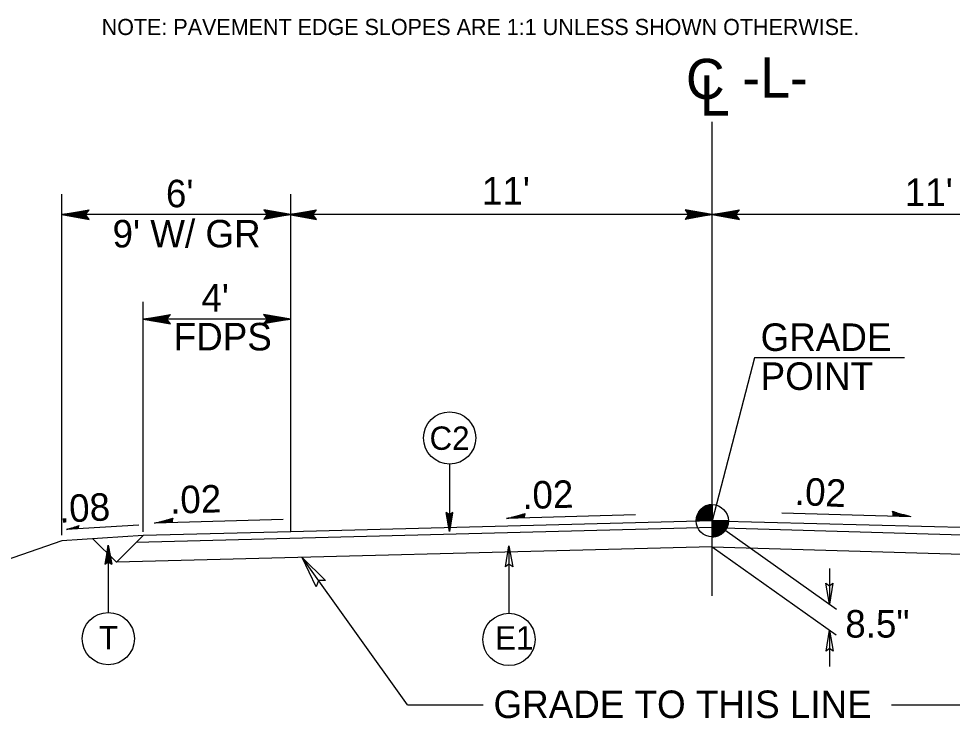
# Model space of a CAD drawing. Extents: x 55823 to 57507, y 47399 to 48499.
# Drawn here: x 56414.9 to 56667.6, y 47890.8 to 48082.1 of the extents above; entities that cross this region are included whole.
import ezdxf

# ---------------------------------------------------------------- set-up
doc = ezdxf.new("R2010")
doc.units = 0
for name, color, linetype in [('Old_Level_1', 7, 'Continuous'), ('Old_Level_11', 7, 'Continuous'), ('Old_Level_2', 7, 'Continuous'), ('Old_Level_20', 7, 'Continuous'), ('Old_Level_3', 7, 'Continuous'), ('Prop Pavement Schedule Description CELL', 7, 'Continuous')]:
    doc.layers.add(name, color=color, linetype=linetype)

msp = doc.modelspace()

# ---------------------------------------------------------------- linework, layer by layer
at = {"layer": 'Old_Level_1'}
for p, q in [((56602.67, 47925.82), (56602.67, 48054.13)), ((56426.62, 47942.28), (56426.62, 48034.56)), ((56488.62, 47943.2), (56488.62, 48034.56)), ((56426.62, 48029.04), (56433.99, 48030.34)), ((56426.62, 48029.04), (56433.85, 48030.15)), ((56433.03, 48029.04), (56433.99, 48030.34)), ((56488.63, 48029.04), (56481.26, 48030.34)), ((56481.26, 48030.34), (56482.22, 48029.04)), ((56481.4, 48030.15), (56488.63, 48029.04)), ((56488.19, 48029.05), (56495.56, 48030.35)), ((56488.19, 48029.05), (56495.42, 48030.16)), ((56494.6, 48029.05), (56495.56, 48030.35)), ((56602.67, 48029.04), (56595.3, 48030.34)), ((56595.3, 48030.34), (56596.26, 48029.04)), ((56595.44, 48030.15), (56602.67, 48029.04)), ((56602.67, 48029.04), (56610.04, 48030.34)), ((56602.67, 48029.04), (56609.9, 48030.15)), ((56609.08, 48029.04), (56610.04, 48030.34)), ((56433.72, 48029.97), (56426.62, 48029.04)), ((56426.62, 48029.04), (56433.58, 48029.78)), ((56433.44, 48029.59), (56426.62, 48029.04)), ((56426.62, 48029.04), (56433.31, 48029.41)), ((56433.17, 48029.23), (56426.62, 48029.04)), ((56426.62, 48029.04), (56433.99, 48027.74)), ((56433.85, 48027.93), (56426.62, 48029.04)), ((56426.62, 48029.04), (56433.72, 48028.11)), ((56433.58, 48028.3), (56426.62, 48029.04)), ((56426.62, 48029.04), (56433.44, 48028.48)), ((56433.31, 48028.67), (56426.62, 48029.04)), ((56426.62, 48029.04), (56433.17, 48028.85)), ((56433.03, 48029.04), (56426.62, 48029.04)), ((56602.67, 48029.04), (56426.62, 48029.04)), ((56433.99, 48027.74), (56433.03, 48029.04)), ((56488.63, 48029.04), (56481.26, 48027.74)), ((56482.22, 48029.04), (56481.26, 48027.74)), ((56488.63, 48029.04), (56481.4, 48027.93)), ((56488.63, 48029.04), (56481.54, 48029.97)), ((56481.54, 48028.11), (56488.63, 48029.04)), ((56481.68, 48029.78), (56488.63, 48029.04)), ((56488.63, 48029.04), (56481.68, 48028.3)), ((56488.63, 48029.04), (56481.81, 48029.6)), ((56481.81, 48028.48), (56488.63, 48029.04)), ((56481.95, 48029.41), (56488.63, 48029.04)), ((56488.63, 48029.04), (56481.95, 48028.67)), ((56488.63, 48029.04), (56482.08, 48029.23)), ((56482.08, 48028.85), (56488.63, 48029.04)), ((56482.22, 48029.04), (56488.63, 48029.04)), ((56495.29, 48029.97), (56488.19, 48029.05)), ((56488.19, 48029.05), (56495.15, 48029.79)), ((56495.01, 48029.6), (56488.19, 48029.05)), ((56488.19, 48029.05), (56494.88, 48029.42)), ((56494.74, 48029.23), (56488.19, 48029.05)), ((56488.19, 48029.05), (56495.56, 48027.75)), ((56495.42, 48027.93), (56488.19, 48029.05)), ((56488.19, 48029.05), (56495.29, 48028.12)), ((56495.15, 48028.3), (56488.19, 48029.05)), ((56488.19, 48029.05), (56495.01, 48028.49)), ((56494.88, 48028.67), (56488.19, 48029.05)), ((56488.19, 48029.05), (56494.74, 48028.86)), ((56494.6, 48029.05), (56488.19, 48029.05)), ((56495.56, 48027.75), (56494.6, 48029.05)), ((56602.67, 48029.04), (56595.3, 48027.74)), ((56596.26, 48029.04), (56595.3, 48027.74)), ((56602.67, 48029.04), (56595.44, 48027.92)), ((56602.67, 48029.04), (56595.58, 48029.97)), ((56595.58, 48028.11), (56602.67, 48029.04)), ((56595.71, 48029.78), (56602.67, 48029.04)), ((56602.67, 48029.04), (56595.71, 48028.3)), ((56602.67, 48029.04), (56595.85, 48029.59)), ((56595.85, 48028.48), (56602.67, 48029.04)), ((56595.98, 48029.41), (56602.67, 48029.04)), ((56602.67, 48029.04), (56595.98, 48028.67)), ((56602.67, 48029.04), (56596.12, 48029.23)), ((56596.12, 48028.85), (56602.67, 48029.04)), ((56596.26, 48029.04), (56602.67, 48029.04)), ((56609.76, 48029.97), (56602.67, 48029.04)), ((56602.67, 48029.04), (56609.63, 48029.78)), ((56609.49, 48029.6), (56602.67, 48029.04)), ((56602.67, 48029.04), (56609.36, 48029.41)), ((56609.22, 48029.23), (56602.67, 48029.04)), ((56602.67, 48029.04), (56610.04, 48027.74)), ((56609.9, 48027.93), (56602.67, 48029.04)), ((56602.67, 48029.04), (56609.76, 48028.11)), ((56609.63, 48028.3), (56602.67, 48029.04)), ((56602.67, 48029.04), (56609.49, 48028.48)), ((56609.36, 48028.67), (56602.67, 48029.04)), ((56602.67, 48029.04), (56609.22, 48028.85)), ((56609.08, 48029.04), (56602.67, 48029.04)), ((56778.32, 48029.04), (56602.67, 48029.04)), ((56610.04, 48027.74), (56609.08, 48029.04)), ((56448.62, 47943.2), (56448.62, 48005.47)), ((56448.62, 48000.75), (56455.99, 48002.05)), ((56448.62, 48000.75), (56455.85, 48001.86)), ((56455.72, 48001.68), (56448.62, 48000.75)), ((56448.62, 48000.75), (56455.58, 48001.49)), ((56455.44, 48001.3), (56448.62, 48000.75)), ((56448.62, 48000.75), (56455.31, 48001.12)), ((56455.17, 48000.94), (56448.62, 48000.75)), ((56488.62, 48000.75), (56448.62, 48000.75)), ((56448.62, 48000.75), (56455.99, 47999.45)), ((56455.85, 47999.64), (56448.62, 48000.75)), ((56448.62, 48000.75), (56455.72, 47999.82)), ((56455.58, 48000.01), (56448.62, 48000.75)), ((56448.62, 48000.75), (56455.44, 48000.19)), ((56455.31, 48000.38), (56448.62, 48000.75)), ((56448.62, 48000.75), (56455.17, 48000.56)), ((56455.03, 48000.75), (56448.62, 48000.75)), ((56455.03, 48000.75), (56455.99, 48002.05)), ((56455.99, 47999.45), (56455.03, 48000.75)), ((56488.62, 48000.75), (56481.25, 48002.05)), ((56481.25, 48002.05), (56482.21, 48000.75)), ((56488.62, 48000.75), (56481.25, 47999.45)), ((56482.21, 48000.75), (56481.25, 47999.45)), ((56481.39, 48001.86), (56488.62, 48000.75)), ((56488.62, 48000.75), (56481.39, 47999.63)), ((56488.62, 48000.75), (56481.53, 48001.68)), ((56481.53, 47999.82), (56488.62, 48000.75)), ((56481.67, 48001.49), (56488.62, 48000.75)), ((56488.62, 48000.75), (56481.67, 48000.01)), ((56488.62, 48000.75), (56481.8, 48001.3)), ((56481.8, 48000.19), (56488.62, 48000.75)), ((56481.94, 48001.12), (56488.62, 48000.75)), ((56488.62, 48000.75), (56481.94, 48000.38)), ((56488.62, 48000.75), (56482.07, 48000.94)), ((56482.07, 48000.56), (56488.62, 48000.75)), ((56482.21, 48000.75), (56488.62, 48000.75)), ((56602.67, 47950.53), (56602.67, 47946.17)), ((56456.47, 47946.7), (56456.4, 47946.69)), ((56456.55, 47946.8), (56456.51, 47946.75)), ((56531.58, 47943.25), (56530.66, 47948.43)), ((56531.58, 47947.76), (56530.66, 47948.43)), ((56531.58, 47943.25), (56530.79, 47948.33)), ((56530.93, 47948.24), (56531.58, 47943.25)), ((56531.58, 47943.25), (56531.06, 47948.14)), ((56531.19, 47948.04), (56531.58, 47943.25)), ((56531.58, 47943.25), (56531.32, 47947.95)), ((56531.45, 47947.85), (56531.58, 47943.25)), ((56531.58, 47943.25), (56532.49, 47948.43)), ((56532.49, 47948.43), (56531.58, 47947.76)), ((56532.36, 47948.33), (56531.58, 47943.25)), ((56531.58, 47943.25), (56532.23, 47948.24)), ((56532.1, 47948.14), (56531.58, 47943.25)), ((56531.58, 47943.25), (56531.97, 47948.04)), ((56531.84, 47947.95), (56531.58, 47943.25)), ((56531.58, 47943.25), (56531.71, 47947.85)), ((56531.58, 47947.76), (56531.58, 47943.25)), ((56581.88, 47947.74), (56546.98, 47946.77)), ((56551.62, 47946.97), (56547.45, 47946.83)), ((56551.63, 47947.06), (56547.82, 47946.91)), ((56551.6, 47947.16), (56548.23, 47947.03)), ((56551.62, 47947.27), (56548.69, 47947.13)), ((56551.62, 47947.37), (56549.01, 47947.22)), ((56551.63, 47947.45), (56549.75, 47947.39)), ((56551.63, 47947.59), (56550.28, 47947.55)), ((56550.81, 47947.69), (56551.67, 47947.73)), ((56551.73, 47947.82), (56551.24, 47947.84)), ((56551.78, 47947.96), (56551.71, 47947.95)), ((56551.86, 47948.06), (56551.82, 47948.01)), ((56621.53, 47948.33), (56656.43, 47947.36)), ((56651.55, 47948.64), (56651.59, 47948.6)), ((56651.63, 47948.54), (56651.7, 47948.54)), ((56651.68, 47948.41), (56652.16, 47948.42)), ((56652.6, 47948.28), (56651.74, 47948.32)), ((56651.77, 47948.04), (56653.66, 47947.97)), ((56651.78, 47948.17), (56653.13, 47948.13)), ((56651.78, 47947.85), (56654.72, 47947.71)), ((56651.78, 47947.65), (56655.59, 47947.5)), ((56651.79, 47947.95), (56654.4, 47947.81)), ((56651.79, 47947.56), (56655.96, 47947.41)), ((56651.81, 47947.75), (56655.18, 47947.61)), ((56447.43, 47945), (56427.87, 47943.82)), ((56430.97, 47944.12), (56428.43, 47943.93)), ((56430.94, 47944.18), (56428.7, 47944.02)), ((56430.96, 47944.25), (56429, 47944.1)), ((56430.95, 47944.32), (56429.21, 47944.17)), ((56430.96, 47944.38), (56429.7, 47944.29)), ((56430.95, 47944.46), (56430.05, 47944.41)), ((56430.41, 47944.52), (56430.98, 47944.56)), ((56431.01, 47944.62), (56430.69, 47944.62)), ((56431.05, 47944.71), (56431, 47944.71)), ((56431.1, 47944.78), (56431.07, 47944.75)), ((56602.67, 47944.33), (56446.74, 47940.28)), ((56486.56, 47946.48), (56451.67, 47945.51)), ((56456.31, 47945.72), (56452.13, 47945.57)), ((56456.32, 47945.8), (56452.51, 47945.65)), ((56456.29, 47945.91), (56452.91, 47945.77)), ((56456.31, 47946.01), (56453.38, 47945.87)), ((56456.31, 47946.11), (56453.69, 47945.96)), ((56456.32, 47946.2), (56454.43, 47946.13)), ((56456.32, 47946.33), (56454.97, 47946.29)), ((56455.5, 47946.44), (56456.36, 47946.47)), ((56456.41, 47946.56), (56455.93, 47946.58)), ((56602.67, 47946.17), (56488.62, 47943.2)), ((56602.67, 47946.17), (56598.31, 47946.17)), ((56607.03, 47946.17), (56602.67, 47946.17)), ((56602.67, 47941.8), (56602.67, 47946.17)), ((56602.67, 47946.17), (56607.03, 47946.17)), ((56602.67, 47946.17), (56716.32, 47943.21)), ((56602.67, 47946.17), (56636.31, 47922.26)), ((56602.67, 47944.33), (56758.78, 47939.72)), ((56448.62, 47942.16), (56426.62, 47940.74)), ((56430.96, 47944.06), (56428.18, 47943.87)), ((56441.4, 47934.94), (56448.62, 47942.16)), ((56488.62, 47943.2), (56448.62, 47942.16)), ((56426.62, 47940.74), (56283.03, 47890.79)), ((56441.4, 47934.94), (56435.05, 47941.28)), ((56439.2, 47939.6), (56438.29, 47934.42)), ((56438.42, 47934.52), (56439.2, 47939.6)), ((56439.2, 47939.6), (56438.55, 47934.61)), ((56438.68, 47934.71), (56439.2, 47939.6)), ((56439.2, 47939.6), (56438.81, 47934.8)), ((56438.94, 47934.9), (56439.2, 47939.6)), ((56439.2, 47939.6), (56439.07, 47934.99)), ((56439.2, 47939.6), (56440.11, 47934.42)), ((56439.2, 47935.09), (56439.2, 47939.6)), ((56439.33, 47934.99), (56439.2, 47939.6)), ((56439.2, 47939.6), (56439.46, 47934.9)), ((56439.59, 47934.8), (56439.2, 47939.6)), ((56439.2, 47939.6), (56439.72, 47934.71)), ((56439.85, 47934.61), (56439.2, 47939.6)), ((56439.2, 47939.6), (56439.98, 47934.52)), ((56602.67, 47939.13), (56441.4, 47934.94)), ((56602.66, 47939.13), (56636.23, 47915.28)), ((56602.67, 47939.13), (56764.12, 47934.38)), ((56438.29, 47934.42), (56439.2, 47935.09)), ((56439.2, 47935.09), (56440.11, 47934.42)), ((56520.17, 47896.36), (56491.67, 47936.25)), ((56520.17, 47896.36), (56540.64, 47896.36)), ((56651.17, 47896.36), (56680.41, 47896.36))]:
    msp.add_line(p, q, dxfattribs=at)
for points in [[(56654.67, 47990.26), (56614.08, 47990.26), (56602.67, 47946.17)], [(56599.51, 47949.18), (56602.67, 47949.18)], [(56599.6, 47949.26), (56602.67, 47949.26)], [(56599.69, 47949.35), (56602.67, 47949.35)], [(56599.78, 47949.44), (56602.67, 47949.44)], [(56599.89, 47949.53), (56602.67, 47949.53)], [(56599.99, 47949.61), (56602.67, 47949.61)], [(56600.11, 47949.7), (56602.67, 47949.7)], [(56600.24, 47949.79), (56602.67, 47949.79)], [(56600.37, 47949.88), (56602.67, 47949.88)], [(56600.52, 47949.96), (56602.67, 47949.96)], [(56600.68, 47950.05), (56602.67, 47950.05)], [(56600.86, 47950.14), (56602.67, 47950.14)], [(56601.06, 47950.23), (56602.67, 47950.22)], [(56601.31, 47950.31), (56602.67, 47950.31)], [(56601.61, 47950.4), (56602.67, 47950.4)], [(56602.05, 47950.49), (56602.67, 47950.49)], [(56598.33, 47946.65), (56602.67, 47946.65)], [(56598.34, 47946.74), (56602.67, 47946.73)], [(56598.36, 47946.82), (56602.67, 47946.82)], [(56598.37, 47946.91), (56602.67, 47946.91)], [(56598.39, 47947), (56602.67, 47947)], [(56598.4, 47947.08), (56602.67, 47947.08)], [(56598.42, 47947.17), (56602.67, 47947.17)], [(56598.45, 47947.26), (56602.67, 47947.26)], [(56598.47, 47947.35), (56602.67, 47947.34)], [(56598.49, 47947.43), (56602.67, 47947.43)], [(56598.52, 47947.52), (56602.67, 47947.52)], [(56598.55, 47947.61), (56602.67, 47947.61)], [(56598.58, 47947.69), (56602.67, 47947.69)], [(56598.62, 47947.78), (56602.67, 47947.78)], [(56598.65, 47947.87), (56602.67, 47947.87)], [(56598.69, 47947.96), (56602.67, 47947.96)], [(56598.73, 47948.04), (56602.67, 47948.04)], [(56598.77, 47948.13), (56602.67, 47948.13)], [(56598.82, 47948.22), (56602.67, 47948.22)], [(56598.87, 47948.31), (56602.67, 47948.31)], [(56598.92, 47948.39), (56602.67, 47948.39)], [(56598.97, 47948.48), (56602.67, 47948.48)], [(56599.03, 47948.57), (56602.67, 47948.57)], [(56599.08, 47948.65), (56602.67, 47948.65)], [(56599.15, 47948.74), (56602.67, 47948.74)], [(56599.21, 47948.83), (56602.67, 47948.83)], [(56599.28, 47948.92), (56602.67, 47948.92)], [(56599.35, 47949), (56602.67, 47949)], [(56599.43, 47949.09), (56602.67, 47949.09)], [(56598.31, 47946.39), (56602.67, 47946.38)], [(56598.31, 47946.3), (56602.67, 47946.3)], [(56598.31, 47946.21), (56598.31, 47946.21), (56602.67, 47946.21)], [(56598.32, 47946.56), (56602.67, 47946.56)], [(56598.32, 47946.47), (56602.67, 47946.47)], [(56602.67, 47946.11), (56607.03, 47946.11), (56607.03, 47946.11)], [(56602.67, 47946.02), (56607.03, 47946.02)], [(56602.67, 47945.93), (56607.02, 47945.93)], [(56602.67, 47945.84), (56607.02, 47945.84)], [(56602.67, 47945.76), (56607.01, 47945.76)], [(56602.67, 47945.67), (56607, 47945.67)], [(56602.67, 47945.58), (56606.99, 47945.58)], [(56602.67, 47945.49), (56606.98, 47945.49)], [(56602.67, 47945.41), (56606.96, 47945.41)], [(56602.67, 47945.32), (56606.95, 47945.32)], [(56602.67, 47945.23), (56606.93, 47945.23)], [(56602.67, 47945.15), (56606.91, 47945.15)], [(56602.67, 47945.06), (56606.89, 47945.06)], [(56602.67, 47944.97), (56606.86, 47944.97)], [(56602.67, 47944.88), (56606.84, 47944.88)], [(56602.67, 47944.8), (56606.81, 47944.8)], [(56602.67, 47944.71), (56606.78, 47944.71)], [(56602.67, 47944.62), (56606.75, 47944.62)], [(56602.67, 47944.54), (56606.72, 47944.54)], [(56602.67, 47944.45), (56606.68, 47944.45)], [(56602.67, 47944.36), (56606.64, 47944.36)], [(56602.67, 47944.27), (56606.6, 47944.27)], [(56602.67, 47944.19), (56606.56, 47944.19)], [(56602.67, 47944.1), (56606.51, 47944.1)], [(56602.67, 47944.01), (56606.46, 47944.01)], [(56602.67, 47943.92), (56606.41, 47943.92)], [(56602.67, 47943.84), (56606.36, 47943.84)], [(56602.67, 47943.75), (56606.3, 47943.75)], [(56602.67, 47943.66), (56606.24, 47943.66)], [(56602.67, 47943.58), (56606.18, 47943.57)], [(56602.67, 47943.49), (56606.11, 47943.49)], [(56602.67, 47943.4), (56606.04, 47943.4)], [(56602.67, 47943.31), (56605.97, 47943.31)], [(56602.67, 47943.23), (56605.89, 47943.23)], [(56602.67, 47943.14), (56605.81, 47943.14)], [(56602.67, 47943.05), (56605.72, 47943.05)], [(56602.67, 47942.97), (56605.63, 47942.96)], [(56602.67, 47942.88), (56605.53, 47942.88)], [(56602.67, 47942.79), (56605.43, 47942.79)], [(56602.67, 47942.7), (56605.32, 47942.7)], [(56602.67, 47942.62), (56605.2, 47942.62)], [(56602.67, 47942.53), (56605.07, 47942.53)], [(56602.67, 47942.44), (56604.94, 47942.44)], [(56602.67, 47942.35), (56604.79, 47942.35)], [(56602.67, 47942.27), (56604.62, 47942.27)], [(56602.67, 47942.18), (56604.44, 47942.18)], [(56602.67, 47942.09), (56604.23, 47942.09)], [(56602.67, 47942), (56603.97, 47942)], [(56602.67, 47941.92), (56603.66, 47941.92)], [(56602.67, 47941.83), (56603.14, 47941.83)]]:
    msp.add_lwpolyline(points, dxfattribs=at)
msp.add_circle((56602.67, 47946.17), 4.36, dxfattribs=at)
for centre, radius, start, end in [((56602.67, 47946.17), 4.36, 89.9905, 179.9905), ((56440.5, 47995.5), 51.22, 282.5916, 288.4254), ((56459.06, 47945.87), 2.6, 156.2047, 184.1523), ((56535.81, 47996.76), 51.22, 282.5916, 288.4254), ((56554.37, 47947.13), 2.6, 156.2047, 184.1523), ((56667.6, 47997.35), 51.22, 251.5746, 257.4084), ((56649.04, 47947.71), 2.6, 355.8477, 23.7953), ((56419.35, 47976.89), 34.15, 284.4455, 290.2792), ((56432.79, 47944.22), 1.73, 158.0586, 186.0062), ((56602.67, 47946.17), 4.36, 269.9905, 359.9905)]:
    msp.add_arc(centre, radius, start, end, dxfattribs=at)
at = {"layer": 'Old_Level_11'}
for points in [[(56546.72, 47933.69), (56547.65, 47939.38), (56548.68, 47933.69), (56547.65, 47934.42)], [(56495.49, 47928.26), (56491.67, 47936.25), (56498.01, 47929.99), (56496.1, 47930)], [(56635.34, 47929.3), (56634.41, 47923.61), (56633.38, 47929.3), (56634.41, 47928.57)], [(56633.47, 47910.88), (56634.4, 47916.57), (56635.44, 47910.88), (56634.4, 47911.61)]]:
    msp.add_lwpolyline(points, close=True, dxfattribs=at)
at = {"layer": 'Old_Level_2'}
for p, q in [((56531.58, 47961.51), (56531.58, 47943.25)), ((56439.2, 47939.6), (56439.2, 47921.33)), ((56547.65, 47939.38), (56547.65, 47921.11)), ((56634.41, 47933.29), (56634.41, 47923.61)), ((56634.4, 47916.57), (56634.4, 47906.76))]:
    msp.add_line(p, q, dxfattribs=at)
for centre in [(56531.58, 47968.58), (56439.2, 47914.26), (56547.65, 47914.05)]:
    msp.add_circle(centre, 7.07, dxfattribs=at)

# ---------------------------------------------------------------- texts
at = {"layer": 'Old_Level_1'}
for s, height, p in [("6'", 7.447, (56454.8, 48031.04)), ("11'", 7.447, (56540.33, 48031.78)), ("11'", 7.447, (56654.79, 48031.38)), ("9' W/ GR ", 7.447, (56440.35, 48020.16)), ("4'", 7.447, (56464.4, 48002.78)), ('FDPS', 7.447, (56456.9, 47992.29)), ('GRADE', 7.447, (56615.76, 47992.15)), ('POINT', 7.447, (56615.76, 47981.6)), ('8.5"', 7.447, (56638.67, 47914.55)), ('GRADE TO THIS LINE', 7.4468, (56543.46, 47892.77))]:
    msp.add_text(s, height=height, dxfattribs=at).set_placement(p)
for s, rotation, p in [(' .02', 1.5917, (56548.57, 47949.26)), (' .02', 357.1962, (56622.12, 47950.65)), (' .02', 1.5917, (56453.26, 47948)), (' .08', 2.8038, (56423.25, 47945.49))]:
    msp.add_text(s, height=7.447, rotation=rotation, dxfattribs=at).set_placement(p)
at = {"layer": 'Old_Level_20'}
for s, height, p in [('C2', 6.327, (56526.15, 47965.37)), ('T', 6.33, (56436.64, 47911.33)), ('E1', 6.327, (56543.9, 47911.3))]:
    msp.add_text(s, height=height, dxfattribs=at).set_placement(p)
at = {"layer": 'Old_Level_3'}
for s, p in [('C    ', (56595.54, 48060.35)), ('-L-', (56610.8, 48060.73)), ('L', (56599.3, 48055.86))]:
    msp.add_text(s, height=10.86, dxfattribs=at).set_placement(p)
at = {"layer": 'Prop Pavement Schedule Description CELL'}
msp.add_text('NOTE: PAVEMENT EDGE SLOPES ARE 1:1 UNLESS SHOWN OTHERWISE.', height=4.3533, dxfattribs=at).set_placement((56437.4, 48077.67))

doc.saveas('drawing.dxf')
